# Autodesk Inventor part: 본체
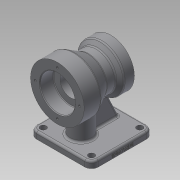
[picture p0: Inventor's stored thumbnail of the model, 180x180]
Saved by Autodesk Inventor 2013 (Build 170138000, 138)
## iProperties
Created: 2019-01
Part Number: 본체
Material: 일반
Document SubType Name: Modeling
Designer: Administrator
Density: 1 g/cm^3
Author: Administrator
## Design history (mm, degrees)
sketch "스케치1"
  geometry: L1 (-30, 0)-(50, 0); L2 (-30, 0)-(-30, 40); L3 (-30, 40)-(-5, 40); L4 (-5, 40)-(15.785, 28); L5 (15.785, 28)-(29.126, 28); L6 (29.126, 28)-(35, 35); L7 (35, 35)-(50, 35); L8 (50, 35)-(50, 0); 1 further point
  constraints: 16 end point, 2 parallel, 2 perpendicular, 1 horizontal, 1 point on line, 1 vertical
  dimensions: "d0" = 25 distance of L2.end L3.end; "d2" = 80 distance between parallel lines of L8 L2; "d3" = 30 deg angle of L5 L4; "d4" = 50 deg angle of L5 L6; "d5" = 15 distance of L6.end L7.end; "d6" = 30 distance from line of L2 point (0, 0); "d7" = 80 diameter of L3 L1; "d8" = 70 diameter of L7 L1; "d9" = 56 diameter of L5 L1
revolve "회전1" sketch "스케치1" stored, may be unused: angle "d10" = 90 deg
hole "구멍1" diameter "d13" = 32; stored, may be unused: countersink angle "d17" = 90 deg, drill point angle "d19" = 118 deg; dims "d14" = 6, "d15" = 52, "d16" = 20, "d18" = 8, "d20" = 10, "d21" = 10
hole "구멍2" diameter "d24" = 40; stored, may be unused: countersink angle "d28" = 90 deg, drill point angle "d30" = 0 deg; dims "d22" = 10, "d23" = 10, "d25" = 6, "d26" = 66, "d27" = 20, "d29" = 17
node "작업 평면1"
sketch "스케치2"
  geometry: L1 (67, -46)-(-25, -46); L2 (-25, -46)-(-25, 46); L3 (-25, 46)-(67, 46); L4 (67, 46)-(67, -46); L5 (67, -46)-(-25, 46); L6 (-25, -46)-(67, 46); 2 further points
  constraints: 12 end point, 2 midpoint, 2 parallel, 2 perpendicular, 1 horizontal
  dimensions: "d32" = 92 distance of L2.end L3.end; "d34" = 25 distance from line of L2 point (0, 0); "d35" = 46 distance from line of L3 point (0, 0)
extrude "돌출1" join sketch "스케치2" distance "d36" = 10; taper "d37" = 0 deg
fillet "모깎기1" dims "d38" = 10
sketch "스케치3"
  geometry: A1 r 10 centre (57, 36) between (67, 36) and (57, 46) reference; A2 r 10 centre (-15, 36) between (-15, 46) and (-25, 36) reference; A3 r 10 centre (-15, -36) between (-25, -36) and (-15, -46) reference; A4 r 10 centre (57, -36) between (57, -46) and (67, -36) reference; 5 further points
  constraints: 4 coincident
hole "구멍3" sketch "스케치3" at (-15, 36), (-15, -36), (57, -36), (57, 36) diameter "d39" = 9; stored, may be unused: countersink angle "d43" = 90 deg, drill point angle "d45" = 0 deg; dims "d40" = 6, "d41" = 66, "d42" = 20, "d44" = 17
sketch "스케치4"
  geometry: L1 (-25, 36)-(-25, -36) reference; C1 r 16 at (5, 0); 1 further point
  constraints: 1 centre point, 1 horizontal alignment, 1 midpoint
  dimensions: "d46" = 32 diameter of C1; "d94" = 30 distance from line of C1.centre L1
extrude "돌출2" join sketch "스케치4" stored distance "d51" = 10; taper "d52" = 0 deg
sketch "스케치5"
  geometry: L1 (-57, -70)-(-42.992, -39.959); L2 (-57, -70)-(15, -70) reference; L3 (-67, -70)-(-57, -70) reference; L4 (-67, -70)-(-67, -80) reference; 1 further point
  constraints: 2 end point, 1 point on line
  dimensions: "d53" = 10 distance of L3.start L1.start; "d54" = 25 deg angle of L4 L1
feature "리브1" sketch "스케치5" dims "d55" = 1, "d56" = 10, "d57" = 0, "d58" = 0, "d59" = 1, "d60" = 1
sketch "스케치6"
  geometry: C1 r 26 at (0, 0) reference; 1 further point
  constraints: 1 horizontal alignment
  dimensions: "d61" = 33 distance of C1.centre point (33, 0)
hole "구멍4" sketch "스케치6" at (33, 0) diameter "d62" = 3.242; stored, may be unused: countersink angle "d66" = 90 deg, drill point angle "d68" = 118 deg; dims "d63" = 9, "d64" = 66, "d65" = 20, "d67" = 11
sketch "스케치7"
  geometry: C1 r 20 at (0, 0) reference; 1 further point
  constraints: 1 vertical alignment
  dimensions: "d72" = 27.5 distance of C1.centre point (0, 27.5)
hole "구멍5" sketch "스케치7" at (0, 27.5) diameter "d73" = 3.242; stored, may be unused: countersink angle "d77" = 90 deg, drill point angle "d79" = 118 deg; dims "d74" = 9, "d75" = 66, "d76" = 20, "d78" = 11
sketch "스케치8"
  geometry: L1 (72, 0)-(0, 0) reference; L2 (-10, 10)-(-10, 0) reference; 2 further points
  constraints: 1 other
  dimensions: "d83" = 4 distance from line of L1 point (36, 4); "d84" = 46 distance from line of L2 point (36, 4)
feature "엠보싱1" sketch "스케치8" dims "d32" = 92, "d34" = 25, "d35" = 46, "d85" = 0.5, "d86" = 0
fillet "모깎기2" dims "d87" = 3
fillet "모깎기3" dims "d88" = 3
chamfer "모따기1" distance "d89" = 1; stored, may be unused: second distance "d90" = 2, angle "d91" = 45 deg
fillet "모깎기4" dims "d92" = 1
fillet "모깎기5" dims "d93" = 0.6
node "솔리드1"
pattern_circular "원형 패턴1" dims angle "d70" = 360 deg
pattern_circular "원형 패턴2" dims angle "d81" = 360 deg
